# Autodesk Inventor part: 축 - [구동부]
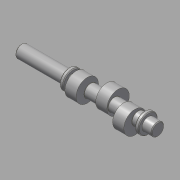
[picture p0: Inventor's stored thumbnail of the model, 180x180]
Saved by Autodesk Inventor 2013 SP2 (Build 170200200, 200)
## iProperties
Company: 한국ATC센터
Created: 2014-08
Part Number: 축 - [구동부]
Document SubType Name: Modeling
Designer: KYOUNG IL JANG
Density: 7.86 g/cm^3
Material: 강철, 연강
Author: KYOUNG IL JANG
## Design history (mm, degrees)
sketch "스케치1"
  geometry: L1 (-91.5, 0)-(91.5, 0); L2 (-91.5, 0)-(-91.5, 8.5); L3 (-91.5, 8.5)-(-27.5, 8.5); L4 (-27.5, 8.5)-(-27.5, 13); L5 (-27.5, 13)-(-22.5, 13); L6 (-22.5, 13)-(-22.5, 8.5); L7 (-22.5, 8.5)-(73.5, 8.5); L8 (73.5, 8.5)-(73.5, 13); L9 (73.5, 13)-(78.5, 13); L10 (78.5, 13)-(78.5, 8.5); L11 (78.5, 8.5)-(91.5, 8.5); L12 (91.5, 8.5)-(91.5, 0); 2 further points
  constraints: 24 end point, 5 parallel, 1 coincident, 1 horizontal, 1 midpoint, 1 perpendicular
  dimensions: "d0" = 183 distance of L1.start L1.end (derived); "d2" = 17 diameter of L3 L1; "d3" = 26 diameter of L5 L1; "d4" = 17 diameter of L7 L1; "d5" = 26 diameter of L9 L1; "d6" = 17 diameter of L11 L1; "d7" = 5 distance of L8.end L9.end; "d8" = 5 distance of L4.end L5.end; "d10" = 64 distance of L2.end L3.end; "d11" = 13 distance of L10.end L11.end; "d35" = 96 distance between parallel lines of L8 L6
revolve "회전1" sketch "스케치1" stored, may be unused: angle "d12" = 90 deg
node "작업 평면7"
sketch "스케치6"
  geometry: C1 r 15 at (0, 5); 1 further point
  constraints: 1 centre point, 1 vertical alignment
  dimensions: "d37" = 30 diameter of C1; "d38" = 5 distance of C1.centre point (0, 0)
extrude "돌출4" join sketch "스케치6" stored distance "d33" = 15; taper "d34" = 0 deg
node "작업 평면8"
sketch "스케치7"
  geometry: L1 (0, 0)-(-6.5, -11.258); L2 (0, 0)-(13, 0); C1 r 15 at (-2.5, -4.33); A1 r 13 centre (0, 0) between (-6.5, -11.258) and (13, 0) reference; 1 further point
  constraints: 4 end point, 2 point on circle, 1 centre point, 1 horizontal, 1 point on line
  dimensions: "d40" = 120 deg angle of L1 L2; "d41" = 30 diameter of C1; "d42" = 5 distance of point (0, 0) C1.centre
extrude "돌출5" join sketch "스케치7" stored distance "d43" = 15; taper "d44" = 0 deg
node "작업 평면9"
sketch "스케치8"
  geometry: L1 (0, 0)-(4.25, -7.361); L2 (0, 0)-(-8.5, 0); C1 r 15 at (2.5, -4.33); A1 r 8.5 centre (0, 0) between (4.25, -7.361) and (-8.5, 0) reference; 1 further point
  constraints: 4 end point, 2 point on circle, 1 centre point, 1 horizontal, 1 point on line
  dimensions: "d46" = 120 deg angle of L1 L2; "d47" = 30 diameter of C1; "d48" = 5 distance of point (0, 0) C1.centre
extrude "돌출6" join sketch "스케치8" stored distance "d49" = 15; taper "d50" = 0 deg
node "작업 평면3"
sketch "스케치5"
  geometry: L1 (32, 8.5)-(32, -8.5) reference; L2 (27.5, -2.5)-(14.5, -2.5); L3 (14.5, 2.5)-(27.5, 2.5); A1 r 2.5 centre (14.5, 0) between (14.5, 2.5) and (14.5, -2.5); A2 r 2.5 centre (27.5, 0) between (27.5, -2.5) and (27.5, 2.5); 4 further points
  constraints: 4 end point, 4 point on circle, 4 tangent, 2 centre point, 2 point on line, 1 horizontal alignment, 1 midpoint, 1 parallel, 1 perpendicular
  dimensions: "d23" = 5 distance between parallel lines of L3 L2; "d36" = 20 dimension on A1 L1; "d52" = 2 distance edge to line of A2 L1
extrude "돌출3" cut sketch "스케치5" distance "d25" = 3; taper "d26" = 0 deg
chamfer "모따기1" distance "d27" = 1; stored, may be unused: second distance "d28" = 2, angle "d29" = 45 deg
fillet "모깎기1" dims "d51" = 0.3
chamfer "모따기2" distance "d53" = 1; stored, may be unused: second distance "d54" = 2, angle "d55" = 45 deg
node "작업 평면10"
node "솔리드1"
other parameters: "d39" = -32, "d45" = 32
